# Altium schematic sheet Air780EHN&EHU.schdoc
size 307 x 218 mm; Symbol: Drawing-Symbol_A4; Device: Drawing-Symbol_A4; Company: 嘉立创EDA; Version: V1.0; Page Size: A4; @Project Name: Air780EPM; @Page Count: 1; @Update Date: 2025-12-16; @Create Date: 2025-12-16; @Schematic Name: Schematic1; @Page No: 1; @Page Name: P1; @Create Time: 10:04:21; @Update Time: 18:04:21; Title Block Position: 3; Size: A4; Width: 1170; Height: 825; Region Start: 1; X Region Count: 6; Y Region Count: 4; Blade Width: 10
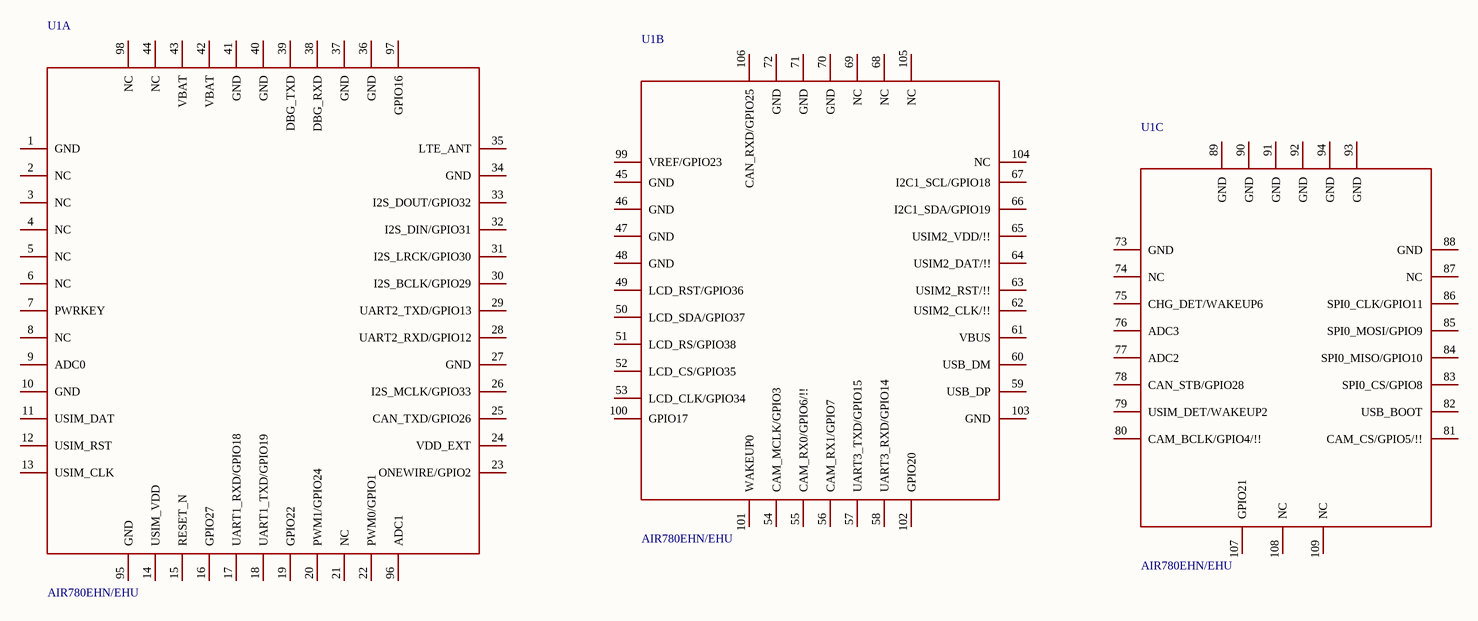
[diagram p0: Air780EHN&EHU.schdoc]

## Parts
U1  AIR780EHN/EHU  [LGA-109_L17.7-W15.8-AIR780E]  (parts A,B,C of 3)

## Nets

Not connected (* = marked no-connect by the designer): U1 1(GND) 2(NC) 3(NC) 4(NC) 5(NC) 6(NC) 7(PWRKEY) 8(NC) 9(ADC0) 10(GND) 11(USIM_DAT) 12(USIM_RST) 13(USIM_CLK) 14(USIM_VDD) 15(RESET_N) 16(GPIO27) 17(UART1_RXD/GPIO18) 18(UART1_TXD/GPIO19) 19(GPIO22) 20(PWM1/GPIO24) 21(NC) 22(PWM0/GPIO1) 23(ONEWIRE/GPIO2) 24(VDD_EXT) 25(CAN_TXD/GPIO26) 26(I2S_MCLK/GPIO33) 27(GND) 28(UART2_RXD/GPIO12) 29(UART2_TXD/GPIO13) 30(I2S_BCLK/GPIO29) 31(I2S_LRCK/GPIO30) 32(I2S_DIN/GPIO31) 33(I2S_DOUT/GPIO32) 34(GND) 35(LTE_ANT) 36(GND) 37(GND) 38(DBG_RXD) 39(DBG_TXD) 40(GND) 41(GND) 42(VBAT) 43(VBAT) 44(NC) 45(GND) 46(GND) 47(GND) 48(GND) 49(LCD_RST/GPIO36) 50(LCD_SDA/GPIO37) 51(LCD_RS/GPIO38) 52(LCD_CS/GPIO35) 53(LCD_CLK/GPIO34) 54(CAM_MCLK/GPIO3) 55(CAM_RX0/GPIO6/!!) 56(CAM_RX1/GPIO7) 57(UART3_TXD/GPIO15) 58(UART3_RXD/GPIO14) 59(USB_DP) 60(USB_DM) 61(VBUS) 62(USIM2_CLK/!!) 63(USIM2_RST/!!) 64(USIM2_DAT/!!) 65(USIM2_VDD/!!) 66(I2C1_SDA/GPIO19) 67(I2C1_SCL/GPIO18) 68(NC) 69(NC) 70(GND) 71(GND) 72(GND) 73(GND) 74(NC) 75(CHG_DET/WAKEUP6) 76(ADC3) 77(ADC2) 78(CAN_STB/GPIO28) 79(USIM_DET/WAKEUP2) 80(CAM_BCLK/GPIO4/!!) 81(CAM_CS/GPIO5/!!) 82(USB_BOOT) 83(SPI0_CS/GPIO8) 84(SPI0_MISO/GPIO10) 85(SPI0_MOSI/GPIO9) 86(SPI0_CLK/GPIO11) 87(NC) 88(GND) 89(GND) 90(GND) 91(GND) 92(GND) 93(GND) 94(GND) 95(GND) 96(ADC1) 97(GPIO16) 98(NC) 99(VREF/GPIO23) 100(GPIO17) 101(WAKEUP0) 102(GPIO20) 103(GND) 104(NC) 105(NC) 106(CAN_RXD/GPIO25) 107(GPIO21) 108(NC) 109(NC)

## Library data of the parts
U1 = AIR780EHN/EHU: Add into BOM: yes; Relevance: []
